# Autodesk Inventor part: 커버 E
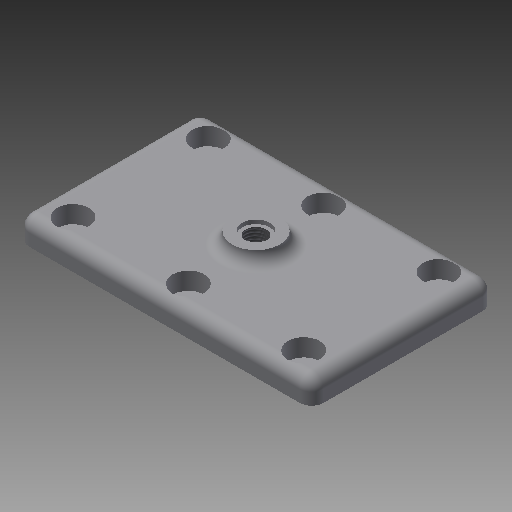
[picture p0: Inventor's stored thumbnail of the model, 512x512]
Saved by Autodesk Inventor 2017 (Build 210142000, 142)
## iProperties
Created: 2020-04
Part Number: 커버 E
Material: 알루미늄 6061
Document SubType Name: Modeling
Designer: mduedu
Density: 2.71 g/cm^3
Appearance: 기본값
Mass: 58.8274 g
Surface Area: 89.9592 cm^2
Volume: 21.7075 cm^3
Author: mduedu
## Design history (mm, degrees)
sketch "스케치1"
  geometry: L1 (37, 23)-(-37, 23); L2 (-37, 23)-(-37, -23); L3 (-37, -23)-(37, -23); L4 (37, -23)-(37, 23); L5 (37, 23)-(-37, -23); L6 (-37, 23)-(37, -23); 1 further point
  constraints: 12 end point, 2 midpoint, 2 parallel, 1 horizontal, 1 perpendicular
  dimensions: "d0" = 74 distance of L3.end L2.end; "d1" = 46 distance of L2.end L1.end
extrude "돌출1" new body sketch "스케치1" distance "d2" = 6; taper "d3" = 0 deg
sketch "스케치2"
  geometry: C1 r 6 at (0, 0); 1 further point
  constraints: 1 centre point, 1 coincident
  dimensions: "d4" = 12 diameter of C1
extrude "돌출2" join sketch "스케치2" distance "d5" = 3; taper "d6" = 0 deg
fillet "모깎기1" dims "d7" = 3
fillet "모깎기2" dims "d8" = 3
fillet "모깎기3" dims "d9" = 3
sketch "스케치3"
  geometry: L1 (-30, -13)-(30, -13); L2 (30, -13)-(30, 13); L3 (30, 13)-(-30, 13); L4 (-30, 13)-(-30, -13); L5 (-30, -13)-(30, 13); L6 (30, -13)-(-30, 13); 1 further point
  constraints: 12 end point, 2 midpoint, 2 parallel, 1 horizontal, 1 perpendicular
  dimensions: "d10" = 60 distance of L3.end L2.end; "d11" = 26 distance of L2.end L1.end
extrude "돌출3" join sketch "스케치3" distance "d12" = 2; taper "d13" = 0 deg
fillet "모깎기4" dims "d14" = 3
chamfer "모따기1" distance "d15" = 0.5; stored, may be unused: second distance "d16" = 2, angle "d17" = 45 deg
sketch "스케치4"
  geometry: L1 (-29, -17)-(29, -17); L2 (29, -17)-(29, 17); L3 (29, 17)-(-29, 17); L4 (-29, 17)-(-29, -17); L5 (-29, -17)-(29, 17); L6 (29, -17)-(-29, 17); 7 further points
  constraints: 12 end point, 4 coincident, 4 midpoint, 2 parallel, 1 horizontal, 1 perpendicular
  dimensions: "d18" = 58 distance of L3.end L2.end; "d19" = 34 distance of L2.end L1.end
hole "구멍1" sketch "스케치4" at (-29, 17), (-29, -17), (29, -17), (29, 17), (0, 17), (0, -17) diameter "d20" = 4.5; stored, may be unused: countersink angle "d24" = 90 deg, drill point angle "d26" = 118 deg; dims "d21" = 6, "d22" = 8, "d23" = 4.4, "d25" = 8
hole "구멍2" diameter "d29" = 5.188; stored, may be unused: countersink angle "d33" = 90 deg, drill point angle "d35" = 118 deg; dims "d27" = 10, "d28" = 10, "d30" = 6, "d31" = 8, "d32" = 4.4, "d34" = 8
sketch "스케치5"
  geometry: C1 r 3.5 at (0, 0); 1 further point
  constraints: 1 centre point, 1 coincident
  dimensions: "d36" = 7 diameter of C1
extrude "돌출4" cut sketch "스케치5" distance "d37" = 1; taper "d38" = 0 deg
node "솔리드1"
